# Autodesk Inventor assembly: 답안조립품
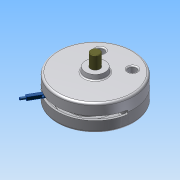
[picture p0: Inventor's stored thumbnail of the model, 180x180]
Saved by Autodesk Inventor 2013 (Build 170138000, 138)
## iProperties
Created: 2015-06
Part Number: 답안조립품
Document SubType Name: Assembly
Designer: Administrator
Author: Administrator
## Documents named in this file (10)
- C:\Documents and Settings\Administrator\바탕 화면\450631V1009\답안조립품.iam
- C:\Documents and Settings\Administrator\바탕 화면\450631V1009\1-본체.ipt
- C:\Documents and Settings\Administrator\바탕 화면\450631V1009\베어링62_22.ipt
- C:\Documents and Settings\Administrator\바탕 화면\450631V1009\축.ipt
- C:\Documents and Settings\Administrator\바탕 화면\450631V1009\덮개.ipt
- C:\Documents and Settings\Administrator\바탕 화면\450631V1009\멈춤링.ipt
- C:\Documents and Settings\Administrator\바탕 화면\450631V1009\평행핀.ipt
- C:\Documents and Settings\Administrator\바탕 화면\450631V1009\슬라이더2.ipt
- C:\Documents and Settings\Administrator\바탕 화면\450631V1009\슬라이더.ipt
- C:\Documents and Settings\Administrator\바탕 화면\450631V1009\M10x35.ipt
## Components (8 placed, 5 different names)
1. 1-본체:1
2. KS B 2023 62/22 - 22 x 50 x 14:1
3. KS B 2023 62/22 - 22 x 50 x 14:2
4. KS B 1336 22 x 1.2:1
5. KS B 1336 22 x 1.2:2
6. KS B 1320 B B 5 x  20:1
7. KS B 1003 - 미터 M 10 x 35:1
8. KS B 1003 - 미터 M 10 x 35:2
